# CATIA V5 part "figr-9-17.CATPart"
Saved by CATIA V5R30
Part number: Part1
Bounding box of the stored display mesh (mm): x -77.304 to 77.304, y -77.304 to 125.507, z 0 to 125
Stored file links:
  D:\PROJECTS\CATIA V56R 2020\Resources\Parts File\c09_catia_v5_6r2020_prt\figr-9-17.CATPart
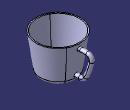
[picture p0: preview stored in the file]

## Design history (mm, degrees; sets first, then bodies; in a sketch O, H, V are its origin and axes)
Set1
  Plane1: type Normal, Curve Sketch3, RefPoint vertex of Sketch3
Body1 (main body)
  Sketch1 on yz-plane, origin (0, 0, 0), H (0, 1, 0), V (0, 0, 1)
    line L1 (0, 0) -> (60, 0)
    point P1 (60, 0)
    point P2 (60, 0)
    line L2 (60, 0) -> (77.5, 125)
    point P3 (77.5, 125)
    line L3 (77.5, 125) -> (0, 125)
    point P4 (0, 125)
    line L4 (0, 125) -> (0, 0)
    axis line L5 (0, 150.2858) -> (0, -31.0593)
    point P5 (0, 150.2858)
    radius about axis P1 L5 = 60
    radius about axis P3 L5 = 77.5
    distance L3 L1 = 125
    horizontal: L1 H, L3 H
    coincidence: P4 V, P2 P1, P5 V
    vertical: L4 V, L5 V
  Shaft1: profile Sketch1, axis Sketch1.L5, angle 360
  Fillet1: radius 15, on edge [face of Shaft1 | face of Shaft1]
  Shell1: ExtOffset 0, Face face of Shaft1, IntOffset 4
  Sketch2 on Plane1, origin (0, 62.9841, 0), H (-1, 0, 0), V (0, 0, 1)
    circle A1 centre (0, 22.002) radius 7.5
    reference projected point E1 (0, 22.002) from vertex of Sketch3
    radius A1 = 7.5
    concentricity: A1 E1
  Sketch3 on yz-plane, origin (0, 0, 0), H (0, 1, 0), V (0, 0, 1)
    line L1 (62.9841, 22.002) -> (78.2172, 22.002)
    arc A1 centre (78.2172, 44.1133) radius 22.1113 from (78.2172, 22.002) to (97.9307, 34.0988) ccw
    arc A2 centre (-112.3295, 140.9107) radius 235.8349 from (97.9307, 34.0988) to (117.8681, 89.6549) ccw
    arc A3 centre (104.0328, 92.7355) radius 14.1742 from (117.8681, 89.6549) to (104.4272, 106.9041) ccw
    arc A4 centre (93.6744, -279.4123) radius 386.4661 from (104.4272, 106.9041) to (82.9216, 106.9041) ccw
    horizontal: L1 H
    tangency: A1 L1, A2 A1, A3 A2, A4 A3
  Rib1: profile Sketch2, centre curve Sketch3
